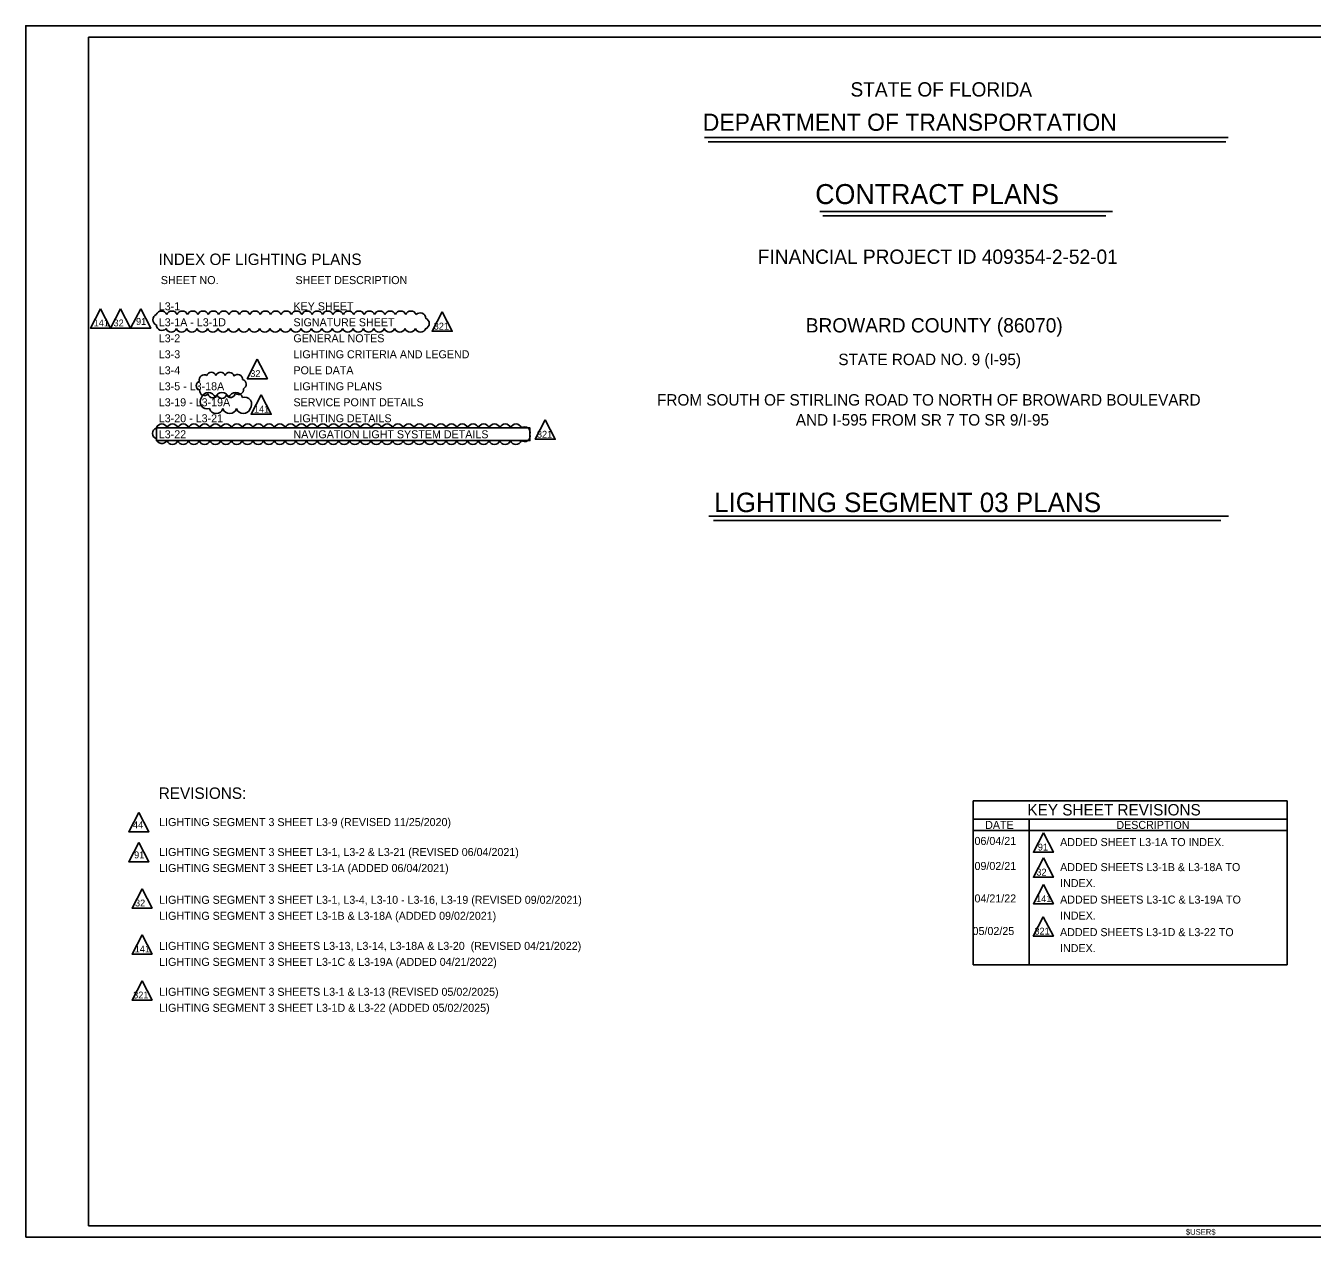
# Model space of a CAD drawing. Extents: x -820.2 to -798.4, y -2199.1 to -2188.5.
# Drawn here: x -820.23 to -808.97, y -2199.12 to -2188.52 of the extents above; entities that cross this region are included whole.
import ezdxf

# ---------------------------------------------------------------- set-up
doc = ezdxf.new("R2010")
doc.units = 0
for name, color, linetype in [('Cloud_dp', 7, 'Continuous'), ('NonPlottingEle_dp', 7, 'Continuous'), ('PlotBorder_dp', 7, 'Continuous'), ('SheetBorder_dp', 7, 'Continuous'), ('SumBoxLines_dp', 7, 'Continuous'), ('TextLabel', 7, 'Continuous'), ('TextMinor', 7, 'Continuous'), ('TextNotes', 7, 'Continuous'), ('TextTitle', 7, 'Continuous')]:
    doc.layers.add(name, color=color, linetype=linetype)

msp = doc.modelspace()

# ---------------------------------------------------------------- linework, layer by layer
at = {"layer": 'Cloud_dp'}
for points in [[(-819.573, -2190.999), (-819.661, -2191.169), (-819.485, -2191.169)], [(-819.397, -2190.999), (-819.485, -2191.169), (-819.309, -2191.169)], [(-819.221, -2191.001), (-819.309, -2191.171), (-819.133, -2191.171)], [(-816.584, -2191.027), (-816.672, -2191.197), (-816.496, -2191.197)], [(-818.201, -2191.442), (-818.289, -2191.612), (-818.113, -2191.612)], [(-818.167, -2191.754), (-818.255, -2191.923), (-818.079, -2191.923)], [(-815.682, -2191.973), (-815.77, -2192.142), (-815.594, -2192.142)], [(-819.238, -2195.406), (-819.326, -2195.576), (-819.15, -2195.576)], [(-819.238, -2195.669), (-819.326, -2195.838), (-819.15, -2195.838)], [(-811.324, -2195.585), (-811.412, -2195.755), (-811.236, -2195.755)], [(-811.324, -2195.804), (-811.412, -2195.973), (-811.236, -2195.973)], [(-819.209, -2196.074), (-819.297, -2196.243), (-819.121, -2196.243)], [(-811.324, -2196.036), (-811.412, -2196.205), (-811.236, -2196.205)], [(-811.325, -2196.32), (-811.413, -2196.489), (-811.237, -2196.489)], [(-819.209, -2196.476), (-819.297, -2196.646), (-819.121, -2196.646)], [(-819.209, -2196.879), (-819.297, -2197.049), (-819.121, -2197.049)]]:
    msp.add_lwpolyline(points, close=True, dxfattribs=at)
for centre, radius, start, end in [((-819.066, -2191.096), 0.0492, 112.5, 247.5), ((-819.039, -2191.069), 0.0492, 22.5, 157.5), ((-818.948, -2191.069), 0.0492, 22.5, 157.5), ((-818.857, -2191.069), 0.0492, 22.5, 157.5), ((-818.766, -2191.069), 0.0492, 22.5, 157.5), ((-818.676, -2191.069), 0.0492, 22.5, 157.5), ((-818.585, -2191.069), 0.0492, 22.5, 157.5), ((-818.494, -2191.069), 0.0492, 22.5, 157.5), ((-818.403, -2191.069), 0.0492, 22.5, 157.5), ((-818.312, -2191.069), 0.0492, 22.5, 157.5), ((-818.221, -2191.069), 0.0492, 22.5, 157.5), ((-818.13, -2191.069), 0.0492, 22.5, 157.5), ((-818.039, -2191.069), 0.0492, 22.5, 157.5), ((-817.948, -2191.069), 0.0492, 22.5, 157.5), ((-817.857, -2191.069), 0.0492, 22.5, 157.5), ((-817.766, -2191.069), 0.0492, 22.5, 157.5), ((-817.676, -2191.069), 0.0492, 22.5, 157.5), ((-817.585, -2191.069), 0.0492, 22.5, 157.5), ((-817.494, -2191.069), 0.0492, 22.5, 157.5), ((-817.403, -2191.069), 0.0492, 22.5, 157.5), ((-817.312, -2191.069), 0.0492, 22.5, 157.5), ((-817.221, -2191.069), 0.0492, 22.5, 157.5), ((-817.13, -2191.069), 0.0492, 22.5, 157.5), ((-817.039, -2191.069), 0.0492, 22.5, 157.5), ((-816.948, -2191.069), 0.0492, 22.5, 157.5), ((-816.857, -2191.069), 0.0492, 22.5, 157.5), ((-816.776, -2191.085), 0.0492, 1.4427, 136.4427), ((-819.035, -2191.14), 0.0492, 181.4427, 316.4427), ((-818.954, -2191.155), 0.0492, 202.5, 337.5), ((-818.863, -2191.155), 0.0492, 202.5, 337.5), ((-818.773, -2191.155), 0.0492, 202.5, 337.5), ((-818.682, -2191.155), 0.0492, 202.5, 337.5), ((-818.591, -2191.155), 0.0492, 202.5, 337.5), ((-818.5, -2191.155), 0.0492, 202.5, 337.5), ((-818.409, -2191.155), 0.0492, 202.5, 337.5), ((-818.318, -2191.155), 0.0492, 202.5, 337.5), ((-818.227, -2191.155), 0.0492, 202.5, 337.5), ((-818.136, -2191.155), 0.0492, 202.5, 337.5), ((-818.045, -2191.155), 0.0492, 202.5, 337.5), ((-817.954, -2191.155), 0.0492, 202.5, 337.5), ((-817.863, -2191.155), 0.0492, 202.5, 337.5), ((-817.773, -2191.155), 0.0492, 202.5, 337.5), ((-817.682, -2191.155), 0.0492, 202.5, 337.5), ((-817.591, -2191.155), 0.0492, 202.5, 337.5), ((-817.5, -2191.155), 0.0492, 202.5, 337.5), ((-817.409, -2191.155), 0.0492, 202.5, 337.5), ((-817.318, -2191.155), 0.0492, 202.5, 337.5), ((-817.227, -2191.155), 0.0492, 202.5, 337.5), ((-817.136, -2191.155), 0.0492, 202.5, 337.5), ((-817.045, -2191.155), 0.0492, 202.5, 337.5), ((-816.954, -2191.155), 0.0492, 202.5, 337.5), ((-816.864, -2191.155), 0.0492, 202.5, 337.5), ((-816.773, -2191.155), 0.0492, 202.5, 337.5), ((-816.746, -2191.129), 0.0492, 292.5, 67.5), ((-818.667, -2191.619), 0.0419, 55.3499, 200.3499), ((-818.603, -2191.597), 0.0419, 17.5, 162.5), ((-818.523, -2191.597), 0.0419, 17.5, 162.5), ((-818.444, -2191.599), 0.0419, 14.5575, 159.5575), ((-818.372, -2191.616), 0.0419, 354.4658, 139.4658), ((-818.339, -2191.661), 0.0419, 292.2226, 77.2226), ((-818.693, -2191.673), 0.0419, 108.9369, 253.9369), ((-818.663, -2191.718), 0.042, 174.0589, 319.0589), ((-818.629, -2191.795), 0.0625, 17.5, 162.5), ((-818.51, -2191.795), 0.0625, 17.5, 162.5), ((-818.435, -2191.734), 0.0419, 208.1049, 353.1049), ((-818.391, -2191.795), 0.0625, 17.5, 162.5), ((-818.364, -2191.708), 0.0419, 226.6409, 11.6409), ((-818.639, -2191.814), 0.0624, 142.3534, 287.3534), ((-818.59, -2191.738), 0.0419, 190.2926, 335.2926), ((-818.512, -2191.742), 0.0419, 198.9922, 343.9922), ((-818.313, -2191.836), 0.0624, 322.3534, 107.3534), ((-818.561, -2191.855), 0.0625, 197.5, 342.5), ((-818.442, -2191.855), 0.0625, 197.5, 342.5), ((-818.323, -2191.855), 0.0625, 197.5, 342.5), ((-819.069, -2192.09), 0.0492, 107.5, 252.5), ((-819.036, -2192.057), 0.0492, 17.5, 162.5), ((-818.943, -2192.057), 0.0492, 17.5, 162.5), ((-818.849, -2192.057), 0.0492, 17.5, 162.5), ((-818.755, -2192.057), 0.0492, 17.5, 162.5), ((-818.661, -2192.057), 0.0492, 17.5, 162.5), ((-818.567, -2192.057), 0.0492, 17.5, 162.5), ((-818.473, -2192.057), 0.0492, 17.5, 162.5), ((-818.379, -2192.057), 0.0492, 17.5, 162.5), ((-818.285, -2192.057), 0.0492, 17.5, 162.5), ((-818.192, -2192.057), 0.0492, 17.5, 162.5), ((-818.098, -2192.057), 0.0492, 17.5, 162.5), ((-818.004, -2192.057), 0.0492, 17.5, 162.5), ((-817.91, -2192.057), 0.0492, 17.5, 162.5), ((-817.816, -2192.057), 0.0492, 17.5, 162.5), ((-817.722, -2192.057), 0.0492, 17.5, 162.5), ((-817.628, -2192.057), 0.0492, 17.5, 162.5), ((-817.534, -2192.057), 0.0492, 17.5, 162.5), ((-817.44, -2192.057), 0.0492, 17.5, 162.5), ((-817.347, -2192.057), 0.0492, 17.5, 162.5), ((-817.253, -2192.057), 0.0492, 17.5, 162.5), ((-817.159, -2192.057), 0.0492, 17.5, 162.5), ((-817.065, -2192.057), 0.0492, 17.5, 162.5), ((-816.971, -2192.057), 0.0492, 17.5, 162.5), ((-816.877, -2192.057), 0.0492, 17.5, 162.5), ((-816.783, -2192.057), 0.0492, 17.5, 162.5), ((-816.689, -2192.057), 0.0492, 17.5, 162.5), ((-816.595, -2192.057), 0.0492, 17.5, 162.5), ((-816.502, -2192.057), 0.0492, 17.5, 162.5), ((-816.408, -2192.057), 0.0492, 17.5, 162.5), ((-816.314, -2192.057), 0.0492, 17.5, 162.5), ((-816.22, -2192.057), 0.0492, 17.5, 162.5), ((-816.126, -2192.057), 0.0492, 17.5, 162.5), ((-816.032, -2192.057), 0.0492, 17.5, 162.5), ((-815.938, -2192.057), 0.0492, 17.5, 162.5), ((-815.863, -2192.082), 0.0492, 340.9042, 125.9042), ((-819.035, -2192.13), 0.0492, 187.6154, 332.6154), ((-818.944, -2192.138), 0.0492, 197.5, 342.5), ((-818.85, -2192.138), 0.0492, 197.5, 342.5), ((-818.756, -2192.138), 0.0492, 197.5, 342.5), ((-818.662, -2192.138), 0.0492, 197.5, 342.5), ((-818.568, -2192.138), 0.0492, 197.5, 342.5), ((-818.475, -2192.138), 0.0492, 197.5, 342.5), ((-818.381, -2192.138), 0.0492, 197.5, 342.5), ((-818.287, -2192.138), 0.0492, 197.5, 342.5), ((-818.193, -2192.138), 0.0492, 197.5, 342.5), ((-818.099, -2192.138), 0.0492, 197.5, 342.5), ((-818.005, -2192.138), 0.0492, 197.5, 342.5), ((-817.911, -2192.138), 0.0492, 197.5, 342.5), ((-817.817, -2192.138), 0.0492, 197.5, 342.5), ((-817.724, -2192.138), 0.0492, 197.5, 342.5), ((-817.63, -2192.138), 0.0492, 197.5, 342.5), ((-817.536, -2192.138), 0.0492, 197.5, 342.5), ((-817.442, -2192.138), 0.0492, 197.5, 342.5), ((-817.348, -2192.138), 0.0492, 197.5, 342.5), ((-817.254, -2192.138), 0.0492, 197.5, 342.5), ((-817.16, -2192.138), 0.0492, 197.5, 342.5), ((-817.066, -2192.138), 0.0492, 197.5, 342.5), ((-816.972, -2192.138), 0.0492, 197.5, 342.5), ((-816.879, -2192.138), 0.0492, 197.5, 342.5), ((-816.785, -2192.138), 0.0492, 197.5, 342.5), ((-816.691, -2192.138), 0.0492, 197.5, 342.5), ((-816.597, -2192.138), 0.0492, 197.5, 342.5), ((-816.503, -2192.138), 0.0492, 197.5, 342.5), ((-816.409, -2192.138), 0.0492, 197.5, 342.5), ((-816.315, -2192.138), 0.0492, 197.5, 342.5), ((-816.221, -2192.138), 0.0492, 197.5, 342.5), ((-816.127, -2192.138), 0.0492, 197.5, 342.5), ((-816.034, -2192.138), 0.0492, 197.5, 342.5), ((-815.94, -2192.138), 0.0492, 197.5, 342.5), ((-815.863, -2192.113), 0.0492, 232.6787, 17.6787)]:
    msp.add_arc(centre, radius, start, end, dxfattribs=at)
at = {"layer": 'NonPlottingEle_dp'}
msp.add_lwpolyline([(-819.083, -2192.043), (-815.816, -2192.043), (-815.816, -2192.153), (-819.083, -2192.153)], close=True, dxfattribs=at)
at = {"layer": 'PlotBorder_dp'}
msp.add_lwpolyline([(-820.227, -2199.124), (-803.727, -2199.124), (-803.727, -2188.524), (-820.227, -2188.524)], close=True, dxfattribs=at)
at = {"layer": 'SheetBorder_dp'}
for p, q in [((-819.677, -2188.624), (-819.677, -2199.024)), ((-819.677, -2188.624), (-804.277, -2188.624)), ((-819.677, -2199.024), (-804.277, -2199.024))]:
    msp.add_line(p, q, dxfattribs=at)
at = {"layer": 'SumBoxLines_dp'}
for p, q in [((-811.938, -2195.306), (-811.938, -2196.739)), ((-811.938, -2195.306), (-809.191, -2195.306)), ((-809.191, -2195.306), (-809.191, -2196.739)), ((-811.938, -2195.466), (-809.191, -2195.466)), ((-811.938, -2195.566), (-809.191, -2195.566)), ((-811.448, -2195.466), (-811.448, -2196.739)), ((-811.938, -2196.739), (-809.191, -2196.739))]:
    msp.add_line(p, q, dxfattribs=at)
at = {"layer": 'TextTitle'}
for p, q in [((-814.289, -2189.5), (-809.707, -2189.5)), ((-814.257, -2189.538), (-809.729, -2189.538)), ((-813.281, -2190.15), (-810.719, -2190.15)), ((-813.253, -2190.188), (-810.777, -2190.188)), ((-814.252, -2192.813), (-809.704, -2192.813)), ((-814.209, -2192.851), (-809.772, -2192.851))]:
    msp.add_line(p, q, dxfattribs=at)

# ---------------------------------------------------------------- texts
at = {"layer": 'Cloud_dp'}
for s, p in [('141', (-819.633, -2191.154)), ('32', (-819.459, -2191.154)), ('91', (-819.262, -2191.141)), ('321', (-816.658, -2191.182)), ('32', (-818.263, -2191.597)), ('141', (-818.231, -2191.909)), ('321', (-815.755, -2192.128)), ('44', (-819.289, -2195.545)), ('91', (-811.373, -2195.74)), ('91', (-819.279, -2195.808)), ('32', (-811.386, -2195.959)), ('141', (-811.388, -2196.191)), ('32', (-819.271, -2196.229)), ('321', (-811.403, -2196.475)), ('141', (-819.273, -2196.631)), ('321', (-819.287, -2197.034))]:
    msp.add_text(s, height=0.06, rotation=0, dxfattribs=at).set_placement(p)
at = {"layer": 'TextLabel'}
for s, height, p in [('FINANCIAL PROJECT ID 409354-2-52-01', 0.125, (-813.823, -2190.607)), ('INDEX OF LIGHTING PLANS', 0.1, (-819.065, -2190.617)), ('L3-1', 0.07, (-819.063, -2191.013)), ('KEY SHEET', 0.07, (-817.885, -2191.013)), ('L3-1A - L3-1D', 0.07, (-819.063, -2191.153)), ('SIGNATURE SHEET', 0.07, (-817.885, -2191.153)), ('BROWARD COUNTY (86070)', 0.125, (-813.403, -2191.207)), ('L3-2', 0.07, (-819.063, -2191.293)), ('GENERAL NOTES', 0.07, (-817.885, -2191.293)), ('L3-3 ', 0.07, (-819.063, -2191.433)), ('LIGHTING CRITERIA AND LEGEND', 0.07, (-817.885, -2191.433)), ('STATE ROAD NO. 9 (I-95)', 0.1, (-813.118, -2191.493)), ('L3-4', 0.07, (-819.063, -2191.573)), ('POLE DATA', 0.07, (-817.885, -2191.573)), ('L3-5 - L3-18A', 0.07, (-819.063, -2191.713)), ('LIGHTING PLANS', 0.07, (-817.885, -2191.713)), ('L3-19 - L3-19A', 0.07, (-819.063, -2191.853)), ('SERVICE POINT DETAILS', 0.07, (-817.885, -2191.853)), ('FROM SOUTH OF STIRLING ROAD TO NORTH OF BROWARD BOULEVARD', 0.1, (-814.704, -2191.847)), ('L3-20 - L3-21', 0.07, (-819.063, -2191.993)), ('LIGHTING DETAILS', 0.07, (-817.885, -2191.993)), ('AND I-595 FROM SR 7 TO SR 9/I-95', 0.1, (-813.49, -2192.022)), ('L3-22', 0.07, (-819.063, -2192.133)), ('NAVIGATION LIGHT SYSTEM DETAILS', 0.07, (-817.885, -2192.133)), ('REVISIONS:', 0.1, (-819.063, -2195.288)), ('KEY SHEET REVISIONS', 0.1, (-811.464, -2195.433))]:
    msp.add_text(s, height=height, dxfattribs=at).set_placement(p)
at = {"layer": 'TextMinor'}
for s, height, p in [('06/04/21', 0.07, (-811.927, -2195.691)), ('ADDED SHEET L3-1A TO INDEX.', 0.07, (-811.178, -2195.701)), ('09/02/21', 0.07, (-811.927, -2195.91)), ('ADDED SHEETS L3-1B & L3-18A TO ', 0.07, (-811.178, -2195.92)), ('INDEX.', 0.07, (-811.178, -2196.06)), ('04/21/22', 0.07, (-811.927, -2196.194)), ('ADDED SHEETS L3-1C & L3-19A TO ', 0.07, (-811.178, -2196.204)), ('INDEX.', 0.07, (-811.178, -2196.344)), ('05/02/25', 0.07, (-811.944, -2196.479)), ('ADDED SHEETS L3-1D & L3-22 TO ', 0.07, (-811.179, -2196.489)), ('INDEX.', 0.07, (-811.179, -2196.629)), ('$USER$', 0.05, (-810.078, -2199.102))]:
    msp.add_text(s, height=height, dxfattribs=at).set_placement(p)
at = {"layer": 'TextNotes'}
for s, height, p in [('SHEET NO.', 0.07, (-819.045, -2190.784)), ('SHEET DESCRIPTION', 0.07, (-817.867, -2190.784)), ('LIGHTING SEGMENT 3 SHEET L3-9 (REVISED 11/25/2020)', 0.06998, (-819.06, -2195.526)), ('DATE', 0.07, (-811.834, -2195.551)), ('DESCRIPTION', 0.07, (-810.686, -2195.551)), ('LIGHTING SEGMENT 3 SHEET L3-1, L3-2 & L3-21 (REVISED 06/04/2021)', 0.06998, (-819.06, -2195.788)), ('LIGHTING SEGMENT 3 SHEET L3-1A (ADDED 06/04/2021)', 0.06998, (-819.06, -2195.928)), ('LIGHTING SEGMENT 3 SHEET L3-1, L3-4, L3-10 - L3-16, L3-19 (REVISED 09/02/2021)', 0.06998, (-819.06, -2196.206)), ('LIGHTING SEGMENT 3 SHEET L3-1B & L3-18A (ADDED 09/02/2021)', 0.06998, (-819.06, -2196.346)), ('LIGHTING SEGMENT 3 SHEETS L3-13, L3-14, L3-18A & L3-20  (REVISED 04/21/2022)', 0.06998, (-819.06, -2196.609)), ('LIGHTING SEGMENT 3 SHEET L3-1C & L3-19A (ADDED 04/21/2022)', 0.06998, (-819.06, -2196.749)), ('LIGHTING SEGMENT 3 SHEETS L3-1 & L3-13 (REVISED 05/02/2025)', 0.06998, (-819.06, -2197.011)), ('LIGHTING SEGMENT 3 SHEET L3-1D & L3-22 (ADDED 05/02/2025)', 0.06998, (-819.06, -2197.151))]:
    msp.add_text(s, height=height, dxfattribs=at).set_placement(p)
at = {"layer": 'TextTitle'}
for s, height, p in [('STATE OF FLORIDA', 0.125, (-813.012, -2189.143)), ('DEPARTMENT OF TRANSPORTATION', 0.15, (-814.304, -2189.443)), ('CONTRACT PLANS', 0.175, (-813.32, -2190.084)), ('LIGHTING SEGMENT 03 PLANS', 0.17, (-814.205, -2192.779))]:
    msp.add_text(s, height=height, dxfattribs=at).set_placement(p)

doc.saveas('drawing.dxf')
